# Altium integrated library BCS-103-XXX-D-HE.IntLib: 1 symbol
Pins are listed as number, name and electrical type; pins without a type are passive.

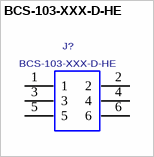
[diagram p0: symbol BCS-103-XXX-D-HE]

## BCS-103-XXX-D-HE
designator J?
BOX CONNECTOR DOUBLE ROW SOCKET STRIP, HORIZONTAL ENTRY.; MANUFACTURER: SAMTEC
footprint BCS-103-XXX-D-HE
pins: 1, 2, 3, 4, 5, 6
